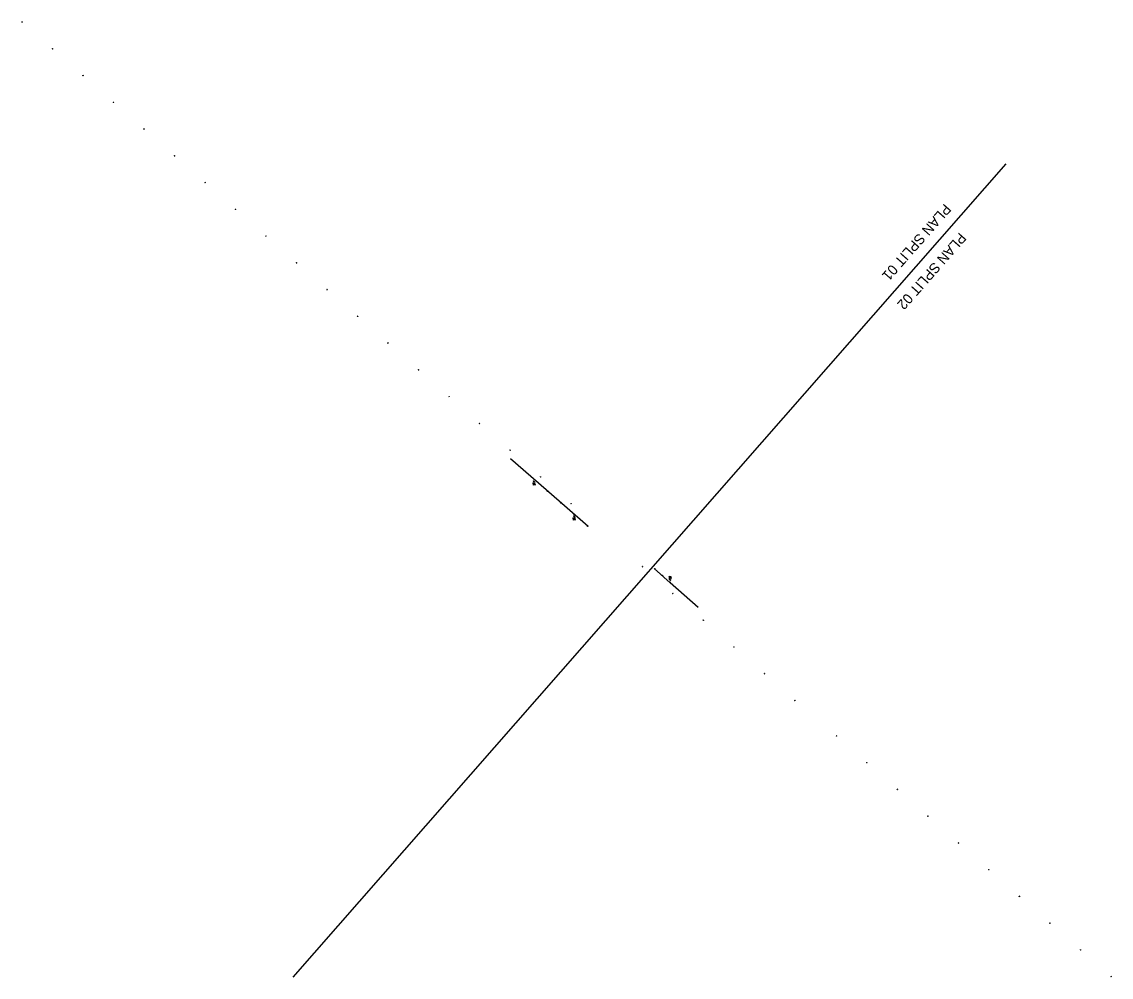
# Model space of a CAD drawing. Extents: x 0 to 963357, y 0 to 528961.
# Drawn here: x 236919 to 239067, y 507467 to 509351 of the extents above; entities that cross this region are included whole.
import ezdxf

# ---------------------------------------------------------------- set-up
doc = ezdxf.new("R2010")
doc.units = 0
for name, color, linetype in [('RW_X_CL_100_Distances', 7, 'Continuous'), ('RW_X_CL_100_Stations', 7, 'Continuous'), ('SC_Scratch2', 7, 'Continuous'), ('SC_Scratch9', 7, 'Continuous')]:
    doc.layers.add(name, color=color, linetype=linetype)

msp = doc.modelspace()

# ---------------------------------------------------------------- linework, layer by layer
at = {"layer": 'RW_X_CL_100_Distances'}
for p, q in [((237952.8, 508428.2), (237882.6, 508489.4)), ((238252.4, 508196.4), (238197.6, 508244.9))]:
    msp.add_line(p, q, dxfattribs=at)
at = {"layer": 'RW_X_CL_100_Stations'}
for p, q in [((238035.5, 508355.9), (237952.8, 508428.2)), ((238197.6, 508244.9), (238165.8, 508272.9))]:
    msp.add_line(p, q, dxfattribs=at)
at = {"layer": 'SC_Scratch2'}
msp.add_line((238859, 509070.6), (237453.1, 507467.4), dxfattribs=at)
at = {"layer": 'SC_Scratch9'}
for p, q in [((236918.8, 509350.4), (236919.1, 509350.1)), ((236918.8, 509350.4), (236919.1, 509350.1)), ((236919.4, 509350.5), (236919.1, 509350.8)), ((236919.1, 509350.8), (236919.4, 509350.5)), ((236919.1, 509350.1), (236919.4, 509350.5)), ((236919.1, 509350.1), (236919.4, 509349.9)), ((236919.4, 509350.5), (236919.7, 509350.3)), ((236979, 509297.7), (236979.2, 509297.4)), ((236979, 509297.7), (236979.2, 509297.4)), ((236979.2, 509297.4), (236979.6, 509297.8)), ((236979.2, 509297.4), (236979.5, 509297.1)), ((236979.6, 509297.8), (236979.3, 509298)), ((236979.3, 509298), (236979.6, 509297.8)), ((236979.6, 509297.8), (236979.9, 509297.5)), ((237039.1, 509244.9), (237039.4, 509244.7)), ((237039.1, 509244.9), (237039.4, 509244.7)), ((237039.7, 509245), (237039.4, 509245.3)), ((237039.4, 509245.3), (237039.7, 509245)), ((237039.4, 509244.7), (237039.7, 509245)), ((237039.4, 509244.7), (237039.7, 509244.4)), ((237039.7, 509245), (237040, 509244.8)), ((237099.3, 509192.2), (237099.5, 509191.9)), ((237099.3, 509192.2), (237099.5, 509191.9)), ((237099.5, 509191.9), (237099.9, 509192.3)), ((237099.5, 509191.9), (237099.8, 509191.7)), ((237099.9, 509192.3), (237099.6, 509192.5)), ((237099.6, 509192.5), (237099.9, 509192.3)), ((237099.9, 509192.3), (237100.2, 509192)), ((237159.4, 509139.4), (237159.7, 509139.2)), ((237159.4, 509139.4), (237159.7, 509139.2)), ((237160, 509139.5), (237159.7, 509139.8)), ((237159.7, 509139.8), (237160, 509139.5)), ((237159.7, 509139.2), (237160, 509139.5)), ((237159.7, 509139.2), (237160, 509138.9)), ((237160, 509139.5), (237160.3, 509139.3)), ((237219.5, 509086.7), (237219.8, 509086.4)), ((237219.5, 509086.7), (237219.8, 509086.4)), ((237219.8, 509086.4), (237220.2, 509086.8)), ((237219.8, 509086.4), (237220.1, 509086.2)), ((237220.2, 509086.8), (237219.9, 509087)), ((237219.9, 509087), (237220.2, 509086.8)), ((237220.2, 509086.8), (237220.4, 509086.5)), ((237279.7, 509033.9), (237280, 509033.7)), ((237279.7, 509033.9), (237280, 509033.7)), ((237280.3, 509034), (237280, 509034.3)), ((237280, 509034.3), (237280.3, 509034)), ((237280, 509033.7), (237280.3, 509034)), ((237280, 509033.7), (237280.3, 509033.4)), ((237280.3, 509034), (237280.6, 509033.8)), ((237339.8, 508981.2), (237340.1, 508980.9)), ((237339.8, 508981.2), (237340.1, 508980.9)), ((237340.1, 508980.9), (237340.5, 508981.3)), ((237340.1, 508980.9), (237340.4, 508980.7)), ((237340.5, 508981.3), (237340.2, 508981.5)), ((237340.2, 508981.5), (237340.5, 508981.3)), ((237340.5, 508981.3), (237340.7, 508981)), ((237400, 508928.4), (237400.3, 508928.2)), ((237400, 508928.4), (237400.3, 508928.2)), ((237400.6, 508928.5), (237400.3, 508928.8)), ((237400.3, 508928.8), (237400.6, 508928.5)), ((237400.3, 508928.2), (237400.6, 508928.5)), ((237400.3, 508928.2), (237400.6, 508927.9)), ((237400.6, 508928.5), (237400.9, 508928.3)), ((237460.1, 508875.7), (237460.4, 508875.4)), ((237460.1, 508875.7), (237460.4, 508875.4)), ((237460.4, 508875.4), (237460.8, 508875.8)), ((237460.4, 508875.4), (237460.7, 508875.2)), ((237460.8, 508875.8), (237460.5, 508876.1)), ((237460.5, 508876.1), (237460.8, 508875.8)), ((237460.8, 508875.8), (237461, 508875.5)), ((237520.3, 508822.9), (237520.6, 508822.7)), ((237520.3, 508822.9), (237520.6, 508822.7)), ((237520.9, 508823.1), (237520.6, 508823.3)), ((237520.6, 508823.3), (237520.9, 508823.1)), ((237520.6, 508822.7), (237520.9, 508823.1)), ((237520.6, 508822.7), (237520.9, 508822.4)), ((237520.9, 508823.1), (237521.2, 508822.8)), ((237580.4, 508770.2), (237580.7, 508769.9)), ((237580.4, 508770.2), (237580.7, 508769.9)), ((237580.7, 508769.9), (237581.1, 508770.3)), ((237580.7, 508769.9), (237581, 508769.7)), ((237581.1, 508770.3), (237580.8, 508770.6)), ((237580.8, 508770.6), (237581.1, 508770.3)), ((237581.1, 508770.3), (237581.3, 508770.1)), ((237640.6, 508717.5), (237640.9, 508717.2)), ((237640.6, 508717.5), (237640.9, 508717.2)), ((237641.2, 508717.6), (237640.9, 508717.8)), ((237640.9, 508717.8), (237641.2, 508717.6)), ((237640.9, 508717.2), (237641.2, 508717.6)), ((237640.9, 508717.2), (237641.2, 508716.9)), ((237641.2, 508717.6), (237641.5, 508717.3)), ((237700.7, 508664.7), (237701, 508664.5)), ((237700.7, 508664.7), (237701, 508664.5)), ((237701, 508664.5), (237701.4, 508664.8)), ((237701, 508664.5), (237701.3, 508664.2)), ((237701.4, 508664.8), (237701.1, 508665.1)), ((237701.1, 508665.1), (237701.4, 508664.8)), ((237701.4, 508664.8), (237701.6, 508664.6)), ((237760.9, 508612), (237761.2, 508611.7)), ((237760.9, 508612), (237761.2, 508611.7)), ((237761.5, 508612.1), (237761.2, 508612.3)), ((237761.2, 508612.3), (237761.5, 508612.1)), ((237761.2, 508611.7), (237761.5, 508612.1)), ((237761.2, 508611.7), (237761.5, 508611.5)), ((237761.5, 508612.1), (237761.8, 508611.8)), ((237821, 508559.2), (237821.3, 508559)), ((237821, 508559.2), (237821.3, 508559)), ((237821.3, 508559), (237821.6, 508559.3)), ((237821.3, 508559), (237821.6, 508558.7)), ((237821.6, 508559.3), (237821.4, 508559.6)), ((237821.4, 508559.6), (237821.6, 508559.3)), ((237821.6, 508559.3), (237821.9, 508559.1)), ((237881.2, 508506.5), (237881.5, 508506.2)), ((237881.2, 508506.5), (237881.5, 508506.2)), ((237881.8, 508506.6), (237881.5, 508506.8)), ((237881.5, 508506.8), (237881.8, 508506.6)), ((237881.5, 508506.2), (237881.8, 508506.6)), ((237881.5, 508506.2), (237881.8, 508506)), ((237881.8, 508506.6), (237882.1, 508506.3)), ((237927.3, 508445.2), (237928, 508445.9)), ((237928.7, 508443.9), (237927.3, 508445.2)), ((237928, 508445.9), (237929.8, 508444.2)), ((237941.3, 508453.7), (237941.6, 508453.5)), ((237941.3, 508453.7), (237941.6, 508453.5)), ((237941.6, 508453.5), (237941.9, 508453.8)), ((237941.6, 508453.5), (237941.9, 508453.2)), ((237941.9, 508453.8), (237941.7, 508454.1)), ((237941.7, 508454.1), (237941.9, 508453.8)), ((237941.9, 508453.8), (237942.2, 508453.6)), ((237925.7, 508443.5), (237925.7, 508443.5)), ((237927.6, 508437.6), (237926.9, 508441.9)), ((237926.9, 508441.9), (237928.3, 508440.1)), ((237931.5, 508438), (237927.6, 508437.6)), ((237928.3, 508440.1), (237928.8, 508440.7)), ((237929.9, 508439.5), (237929.4, 508439)), ((237929.4, 508439), (237931.5, 508438)), ((237931.5, 508438), (237931.5, 508438)), ((237954.6, 508425.5), (237954.9, 508425.2)), ((237954.6, 508425.5), (237954.9, 508425.2)), ((237955.2, 508425.6), (237954.9, 508425.9)), ((237954.9, 508425.9), (237955.2, 508425.6)), ((237954.9, 508425.2), (237955.2, 508425.6)), ((237954.9, 508425.2), (237955.2, 508425)), ((237955.2, 508425.6), (237955.5, 508425.4)), ((237981.1, 508402.4), (237981.4, 508402.1)), ((237981.1, 508402.4), (237981.4, 508402.1)), ((237981.7, 508402.5), (237981.4, 508402.7)), ((237981.4, 508402.7), (237981.7, 508402.5)), ((237981.4, 508402.1), (237981.7, 508402.5)), ((237981.4, 508402.1), (237981.7, 508401.9)), ((237981.7, 508402.5), (237982, 508402.2)), ((238001.5, 508401), (238001.8, 508400.7)), ((238001.5, 508401), (238001.8, 508400.7)), ((238002.1, 508401.1), (238001.8, 508401.3)), ((238001.8, 508401.3), (238002.1, 508401.1)), ((238001.8, 508400.7), (238002.1, 508401.1)), ((238001.8, 508400.7), (238002.1, 508400.5)), ((238002.1, 508401.1), (238002.4, 508400.8)), ((238004.8, 508374.3), (238004.8, 508374.3)), ((238006.7, 508368.4), (238006, 508372.7)), ((238006, 508372.7), (238007.4, 508370.9)), ((238006.4, 508376), (238007.1, 508376.7)), ((238007.8, 508374.7), (238006.4, 508376)), ((238010.6, 508368.8), (238006.7, 508368.4)), ((238007.1, 508376.7), (238008.9, 508375)), ((238007.4, 508370.9), (238007.8, 508371.4)), ((238007.6, 508379.3), (238007.9, 508379)), ((238007.6, 508379.3), (238007.9, 508379)), ((238008.2, 508379.4), (238007.9, 508379.6)), ((238007.9, 508379.6), (238008.2, 508379.4)), ((238007.9, 508379), (238008.2, 508379.4)), ((238007.9, 508379), (238008.1, 508378.7)), ((238008.2, 508379.4), (238008.5, 508379.1)), ((238009, 508370.3), (238008.5, 508369.8)), ((238008.5, 508369.8), (238010.6, 508368.8)), ((238010.6, 508368.8), (238010.6, 508368.8)), ((238034.1, 508356.1), (238034.3, 508355.9)), ((238034.1, 508356.1), (238034.3, 508355.9)), ((238034.3, 508355.9), (238034.7, 508356.2)), ((238034.3, 508355.9), (238034.6, 508355.6)), ((238034.7, 508356.2), (238034.4, 508356.5)), ((238034.4, 508356.5), (238034.7, 508356.2)), ((238034.7, 508356.2), (238035, 508356)), ((238142, 508276.8), (238142.3, 508276.5)), ((238142, 508276.8), (238142.3, 508276.5)), ((238142.6, 508276.9), (238142.3, 508277.1)), ((238142.3, 508277.1), (238142.6, 508276.9)), ((238142.3, 508276.5), (238142.6, 508276.9)), ((238142.3, 508276.5), (238142.5, 508276.3)), ((238142.6, 508276.9), (238142.9, 508276.6)), ((238166.7, 508272.5), (238167, 508272.3)), ((238166.7, 508272.5), (238167, 508272.3)), ((238167.3, 508272.7), (238167, 508272.9)), ((238167, 508272.9), (238167.3, 508272.7)), ((238167, 508272.3), (238167.3, 508272.7)), ((238167, 508272.3), (238167.3, 508272)), ((238167.3, 508272.7), (238167.6, 508272.4)), ((238181.6, 508259.4), (238181.9, 508259.2)), ((238181.6, 508259.4), (238181.9, 508259.2)), ((238181.9, 508259.2), (238182.3, 508259.6)), ((238181.9, 508259.2), (238182.2, 508258.9)), ((238182.3, 508259.6), (238182, 508259.8)), ((238182, 508259.8), (238182.3, 508259.6)), ((238182.3, 508259.6), (238182.6, 508259.3)), ((238194.5, 508257.1), (238198.4, 508257.5)), ((238194.5, 508257.1), (238194.5, 508257.1)), ((238196.5, 508256), (238194.5, 508257.1)), ((238196.1, 508255.5), (238196.5, 508256)), ((238197.7, 508254.9), (238197.2, 508254.4)), ((238199.1, 508253.1), (238197.7, 508254.9)), ((238198.4, 508257.5), (238199.1, 508253.1)), ((238200.3, 508251.6), (238200.3, 508251.6)), ((238198, 508249.2), (238196.2, 508250.9)), ((238196.7, 508246.3), (238197, 508246)), ((238196.7, 508246.3), (238197, 508246)), ((238197.3, 508246.4), (238197, 508246.6)), ((238197, 508246.6), (238197.3, 508246.4)), ((238197, 508246), (238197.3, 508246.4)), ((238197, 508246), (238197.2, 508245.8)), ((238197.3, 508251.2), (238198.7, 508249.9)), ((238197.3, 508246.4), (238197.6, 508246.1)), ((238198.7, 508249.9), (238198, 508249.2)), ((238202.1, 508224), (238202.4, 508223.8)), ((238202.1, 508224), (238202.4, 508223.8)), ((238202.7, 508224.1), (238202.4, 508224.4)), ((238202.4, 508224.4), (238202.7, 508224.1)), ((238202.4, 508223.8), (238202.7, 508224.1)), ((238202.4, 508223.8), (238202.7, 508223.5)), ((238202.7, 508224.1), (238203, 508223.9)), ((238262.3, 508171.3), (238262.6, 508171)), ((238262.3, 508171.3), (238262.6, 508171)), ((238262.9, 508171.4), (238262.6, 508171.7)), ((238262.6, 508171.7), (238262.9, 508171.4)), ((238262.6, 508171), (238262.9, 508171.4)), ((238262.6, 508171), (238262.8, 508170.8)), ((238262.9, 508171.4), (238263.2, 508171.1)), ((238322.4, 508118.5), (238322.7, 508118.3)), ((238322.4, 508118.5), (238322.7, 508118.3)), ((238323, 508118.7), (238322.7, 508118.9)), ((238322.7, 508118.9), (238323, 508118.7)), ((238322.7, 508118.3), (238323, 508118.7)), ((238322.7, 508118.3), (238323, 508118)), ((238323, 508118.7), (238323.3, 508118.4)), ((238382.6, 508065.8), (238382.9, 508065.5)), ((238382.6, 508065.8), (238382.9, 508065.5)), ((238383.2, 508065.9), (238382.9, 508066.2)), ((238382.9, 508066.2), (238383.2, 508065.9)), ((238382.9, 508065.5), (238383.2, 508065.9)), ((238382.9, 508065.5), (238383.1, 508065.3)), ((238383.2, 508065.9), (238383.5, 508065.7)), ((238442.7, 508013.1), (238443, 508012.8)), ((238442.7, 508013.1), (238443, 508012.8)), ((238443.3, 508013.2), (238443, 508013.4)), ((238443, 508013.4), (238443.3, 508013.2)), ((238443, 508012.8), (238443.3, 508013.2)), ((238443, 508012.8), (238443.3, 508012.5)), ((238443.3, 508013.2), (238443.6, 508012.9)), ((238524.4, 507943.1), (238524.7, 507942.9)), ((238524.4, 507943.1), (238524.7, 507942.9)), ((238525, 507943.2), (238524.7, 507943.5)), ((238524.7, 507943.5), (238525, 507943.2)), ((238524.7, 507942.9), (238525, 507943.2)), ((238524.7, 507942.9), (238525, 507942.6)), ((238525, 507943.2), (238525.3, 507943)), ((238584.6, 507890.4), (238584.8, 507890.1)), ((238584.6, 507890.4), (238584.8, 507890.1)), ((238584.8, 507890.1), (238585.2, 507890.5)), ((238584.8, 507890.1), (238585.1, 507889.9)), ((238585.2, 507890.5), (238584.9, 507890.8)), ((238584.9, 507890.8), (238585.2, 507890.5)), ((238585.2, 507890.5), (238585.5, 507890.2)), ((238644.7, 507837.6), (238645, 507837.4)), ((238644.7, 507837.6), (238645, 507837.4)), ((238645.3, 507837.8), (238645, 507838)), ((238645, 507838), (238645.3, 507837.8)), ((238645, 507837.4), (238645.3, 507837.8)), ((238645, 507837.4), (238645.3, 507837.1)), ((238645.3, 507837.8), (238645.6, 507837.5)), ((238704.9, 507784.9), (238705.1, 507784.6)), ((238704.9, 507784.9), (238705.1, 507784.6)), ((238705.1, 507784.6), (238705.5, 507785)), ((238705.1, 507784.6), (238705.4, 507784.4)), ((238705.5, 507785), (238705.2, 507785.3)), ((238705.2, 507785.3), (238705.5, 507785)), ((238705.5, 507785), (238705.8, 507784.7)), ((238765, 507732.2), (238765.3, 507731.9)), ((238765, 507732.2), (238765.3, 507731.9)), ((238765.6, 507732.3), (238765.3, 507732.5)), ((238765.3, 507732.5), (238765.6, 507732.3)), ((238765.3, 507731.9), (238765.6, 507732.3)), ((238765.3, 507731.9), (238765.6, 507731.6)), ((238765.6, 507732.3), (238765.9, 507732)), ((238825.2, 507679.4), (238825.4, 507679.2)), ((238825.2, 507679.4), (238825.4, 507679.2)), ((238825.4, 507679.2), (238825.8, 507679.5)), ((238825.4, 507679.2), (238825.7, 507678.9)), ((238825.8, 507679.5), (238825.5, 507679.8)), ((238825.5, 507679.8), (238825.8, 507679.5)), ((238825.8, 507679.5), (238826.1, 507679.3)), ((238885.3, 507626.7), (238885.6, 507626.4)), ((238885.3, 507626.7), (238885.6, 507626.4)), ((238885.9, 507626.8), (238885.6, 507627)), ((238885.6, 507627), (238885.9, 507626.8)), ((238885.6, 507626.4), (238885.9, 507626.8)), ((238885.6, 507626.4), (238885.9, 507626.1)), ((238885.9, 507626.8), (238886.2, 507626.5)), ((238945.5, 507574), (238945.8, 507573.7)), ((238945.5, 507574), (238945.8, 507573.7)), ((238946.1, 507574.1), (238945.8, 507574.3)), ((238945.8, 507574.3), (238946.1, 507574.1)), ((238945.8, 507573.7), (238946.1, 507574.1)), ((238945.8, 507573.7), (238946.1, 507573.4)), ((238946.1, 507574.1), (238946.4, 507573.8)), ((239005.8, 507521.4), (239006.1, 507521.1)), ((239005.8, 507521.4), (239006.1, 507521.1)), ((239006.4, 507521.5), (239006.1, 507521.7)), ((239006.1, 507521.7), (239006.4, 507521.5)), ((239006.1, 507521.1), (239006.4, 507521.5)), ((239006.4, 507521.5), (239006.7, 507521.2)), ((239006.1, 507521.1), (239006.4, 507520.8)), ((239066.1, 507468.7), (239066.3, 507468.5)), ((239066.1, 507468.7), (239066.3, 507468.5)), ((239066.3, 507468.5), (239066.7, 507468.9)), ((239066.3, 507468.5), (239066.6, 507468.2)), ((239066.7, 507468.9), (239066.4, 507469.1)), ((239066.4, 507469.1), (239066.7, 507468.9)), ((239066.7, 507468.9), (239067, 507468.6))]:
    msp.add_line(p, q, dxfattribs=at)
for centre, radius, start, end in [((236918.9, 509350.7), 0.288, 260.7256, 16.7779), ((236918.9, 509350.7), 0.288, 260.7256, 16.7779), ((236919.7, 509350), 0.288, 80.7256, 196.7779), ((236979, 509297.9), 0.288, 260.7256, 16.7779), ((236979, 509297.9), 0.288, 260.7256, 16.7779), ((236979.8, 509297.2), 0.288, 80.7256, 196.7779), ((237039.1, 509245.2), 0.288, 260.7256, 16.7779), ((237039.1, 509245.2), 0.288, 260.7256, 16.7779), ((237040, 509244.5), 0.288, 80.7256, 196.7779), ((237099.3, 509192.4), 0.288, 260.7256, 16.7779), ((237099.3, 509192.4), 0.288, 260.7256, 16.7779), ((237100.1, 509191.7), 0.288, 80.7256, 196.7779), ((237159.4, 509139.7), 0.288, 260.7256, 16.7779), ((237159.4, 509139.7), 0.288, 260.7256, 16.7779), ((237160.3, 509139), 0.288, 80.7256, 196.7779), ((237219.6, 509087), 0.288, 260.7256, 16.7779), ((237219.6, 509087), 0.288, 260.7256, 16.7779), ((237220.4, 509086.2), 0.288, 80.7256, 196.7779), ((237279.7, 509034.2), 0.288, 260.7256, 16.7779), ((237279.7, 509034.2), 0.288, 260.7256, 16.7779), ((237280.6, 509033.5), 0.288, 80.7256, 196.7779), ((237339.9, 508981.5), 0.288, 260.7256, 16.7779), ((237339.9, 508981.5), 0.288, 260.7256, 16.7779), ((237340.7, 508980.8), 0.288, 80.7256, 196.7779), ((237400, 508928.7), 0.288, 260.7256, 16.7779), ((237400, 508928.7), 0.288, 260.7256, 16.7779), ((237400.8, 508928), 0.288, 80.7256, 196.7779), ((237460.2, 508876), 0.288, 260.7256, 16.7779), ((237460.2, 508876), 0.288, 260.7256, 16.7779), ((237461, 508875.3), 0.288, 80.7256, 196.7779), ((237520.3, 508823.2), 0.288, 260.7256, 16.7779), ((237520.3, 508823.2), 0.288, 260.7256, 16.7779), ((237521.1, 508822.5), 0.288, 80.7256, 196.7779), ((237580.5, 508770.5), 0.288, 260.7256, 16.7779), ((237580.5, 508770.5), 0.288, 260.7256, 16.7779), ((237581.3, 508769.8), 0.288, 80.7256, 196.7779), ((237640.6, 508717.7), 0.288, 260.7256, 16.7779), ((237640.6, 508717.7), 0.288, 260.7256, 16.7779), ((237641.4, 508717), 0.288, 80.7256, 196.7779), ((237700.8, 508665), 0.288, 260.7256, 16.7779), ((237700.8, 508665), 0.288, 260.7256, 16.7779), ((237701.6, 508664.3), 0.288, 80.7256, 196.7779), ((237760.9, 508612.2), 0.288, 260.7256, 16.7779), ((237760.9, 508612.2), 0.288, 260.7256, 16.7779), ((237761.7, 508611.5), 0.288, 80.7256, 196.7779), ((237821.1, 508559.5), 0.288, 260.7256, 16.7779), ((237821.1, 508559.5), 0.288, 260.7256, 16.7779), ((237821.9, 508558.8), 0.288, 80.7256, 196.7779), ((237881.2, 508506.8), 0.288, 260.7256, 16.7779), ((237881.2, 508506.8), 0.288, 260.7256, 16.7779), ((237882, 508506), 0.288, 80.7256, 196.7779), ((237941.4, 508454), 0.288, 260.7256, 16.7779), ((237941.4, 508454), 0.288, 260.7256, 16.7779), ((237942.2, 508453.3), 0.288, 80.7256, 196.7779), ((237927.1, 508442.2), 2.3, 316.7001, 46.7001), ((237927.5, 508441.8), 3.28, 315.7916, 46.7001), ((237954.6, 508425.8), 0.288, 260.7256, 16.7779), ((237954.6, 508425.8), 0.288, 260.7256, 16.7779), ((237955.5, 508425.1), 0.288, 80.7256, 196.7779), ((237981.1, 508402.7), 0.288, 260.7256, 16.7779), ((237981.1, 508402.7), 0.288, 260.7256, 16.7779), ((237981.9, 508401.9), 0.288, 80.7256, 196.7779), ((238001.5, 508401.3), 0.288, 260.7256, 16.7779), ((238001.5, 508401.3), 0.288, 260.7256, 16.7779), ((238002.3, 508400.6), 0.288, 80.7256, 196.7779), ((238007.6, 508379.5), 0.288, 260.7256, 16.7779), ((238007.6, 508379.5), 0.288, 260.7256, 16.7779), ((238006.2, 508373), 2.3, 316.7001, 46.7001), ((238008.4, 508378.8), 0.288, 80.7256, 196.7779), ((238006.6, 508372.6), 3.28, 315.7916, 46.7001), ((238034.1, 508356.4), 0.288, 260.7256, 16.7779), ((238034.1, 508356.4), 0.288, 260.7256, 16.7779), ((238034.9, 508355.7), 0.288, 80.7256, 196.7779), ((238142, 508277.1), 0.288, 260.7256, 16.7779), ((238142, 508277.1), 0.288, 260.7256, 16.7779), ((238142.8, 508276.4), 0.288, 80.7256, 196.7779), ((238166.8, 508272.8), 0.288, 260.7256, 16.7779), ((238166.8, 508272.8), 0.288, 260.7256, 16.7779), ((238167.6, 508272.1), 0.288, 80.7256, 196.7779), ((238181.7, 508259.7), 0.288, 260.7256, 16.7779), ((238181.7, 508259.7), 0.288, 260.7256, 16.7779), ((238182.5, 508259), 0.288, 80.7256, 196.7779), ((238198.4, 508253.2), 3.28, 135.7916, 226.7001), ((238198.9, 508252.8), 2.3, 136.7001, 226.7001), ((238196.7, 508246.6), 0.288, 260.7256, 16.7779), ((238196.7, 508246.6), 0.288, 260.7256, 16.7779), ((238197.5, 508245.9), 0.288, 80.7256, 196.7779), ((238202.2, 508224.3), 0.288, 260.7256, 16.7779), ((238202.2, 508224.3), 0.288, 260.7256, 16.7779), ((238203, 508223.6), 0.288, 80.7256, 196.7779), ((238262.3, 508171.6), 0.288, 260.7256, 16.7779), ((238262.3, 508171.6), 0.288, 260.7256, 16.7779), ((238263.1, 508170.9), 0.288, 80.7256, 196.7779), ((238322.5, 508118.8), 0.288, 260.7256, 16.7779), ((238322.5, 508118.8), 0.288, 260.7256, 16.7779), ((238323.3, 508118.1), 0.288, 80.7256, 196.7779), ((238382.6, 508066.1), 0.288, 260.7256, 16.7779), ((238382.6, 508066.1), 0.288, 260.7256, 16.7779), ((238383.4, 508065.4), 0.288, 80.7256, 196.7779), ((238442.8, 508013.3), 0.288, 260.7256, 16.7779), ((238442.8, 508013.3), 0.288, 260.7256, 16.7779), ((238443.6, 508012.6), 0.288, 80.7256, 196.7779), ((238524.5, 507943.4), 0.288, 259.9104, 15.9627), ((238524.5, 507943.4), 0.288, 259.9104, 15.9627), ((238525.3, 507942.7), 0.288, 79.9104, 195.9627), ((238584.6, 507890.7), 0.288, 259.9104, 15.9627), ((238584.6, 507890.7), 0.288, 259.9104, 15.9627), ((238585.4, 507890), 0.288, 79.9104, 195.9627), ((238644.8, 507837.9), 0.288, 259.9104, 15.9627), ((238644.8, 507837.9), 0.288, 259.9104, 15.9627), ((238645.6, 507837.2), 0.288, 79.9104, 195.9627), ((238704.9, 507785.2), 0.288, 259.9104, 15.9627), ((238704.9, 507785.2), 0.288, 259.9104, 15.9627), ((238705.7, 507784.5), 0.288, 79.9104, 195.9627), ((238765.1, 507732.4), 0.288, 259.9104, 15.9627), ((238765.1, 507732.4), 0.288, 259.9104, 15.9627), ((238765.9, 507731.7), 0.288, 79.9104, 195.9627), ((238825.2, 507679.7), 0.288, 259.9104, 15.9627), ((238825.2, 507679.7), 0.288, 259.9104, 15.9627), ((238826, 507679), 0.288, 79.9104, 195.9627), ((238885.4, 507626.9), 0.288, 259.9104, 15.9627), ((238885.4, 507626.9), 0.288, 259.9104, 15.9627), ((238886.2, 507626.2), 0.288, 79.9104, 195.9627), ((238945.6, 507574.2), 0.288, 260.0428, 16.0952), ((238945.6, 507574.2), 0.288, 260.0428, 16.0952), ((238946.4, 507573.5), 0.288, 80.0428, 196.0952), ((239005.8, 507521.6), 0.288, 260.0428, 16.0952), ((239005.8, 507521.6), 0.288, 260.0428, 16.0952), ((239006.6, 507520.9), 0.288, 80.0428, 196.0952), ((239066.1, 507469), 0.288, 260.0428, 16.0952), ((239066.1, 507469), 0.288, 260.0428, 16.0952), ((239066.9, 507468.3), 0.288, 80.0428, 196.0952)]:
    msp.add_arc(centre, radius, start, end, dxfattribs=at)

# ---------------------------------------------------------------- texts
at = {"layer": 'SC_Scratch2'}
for s, p in [('PLAN SPLIT 01', (238738.1, 508993.4)), ('PLAN SPLIT 02', (238768, 508936.5))]:
    msp.add_text(s, height=20, rotation=228.7518, dxfattribs=at).set_placement(p)

doc.saveas('drawing.dxf')
